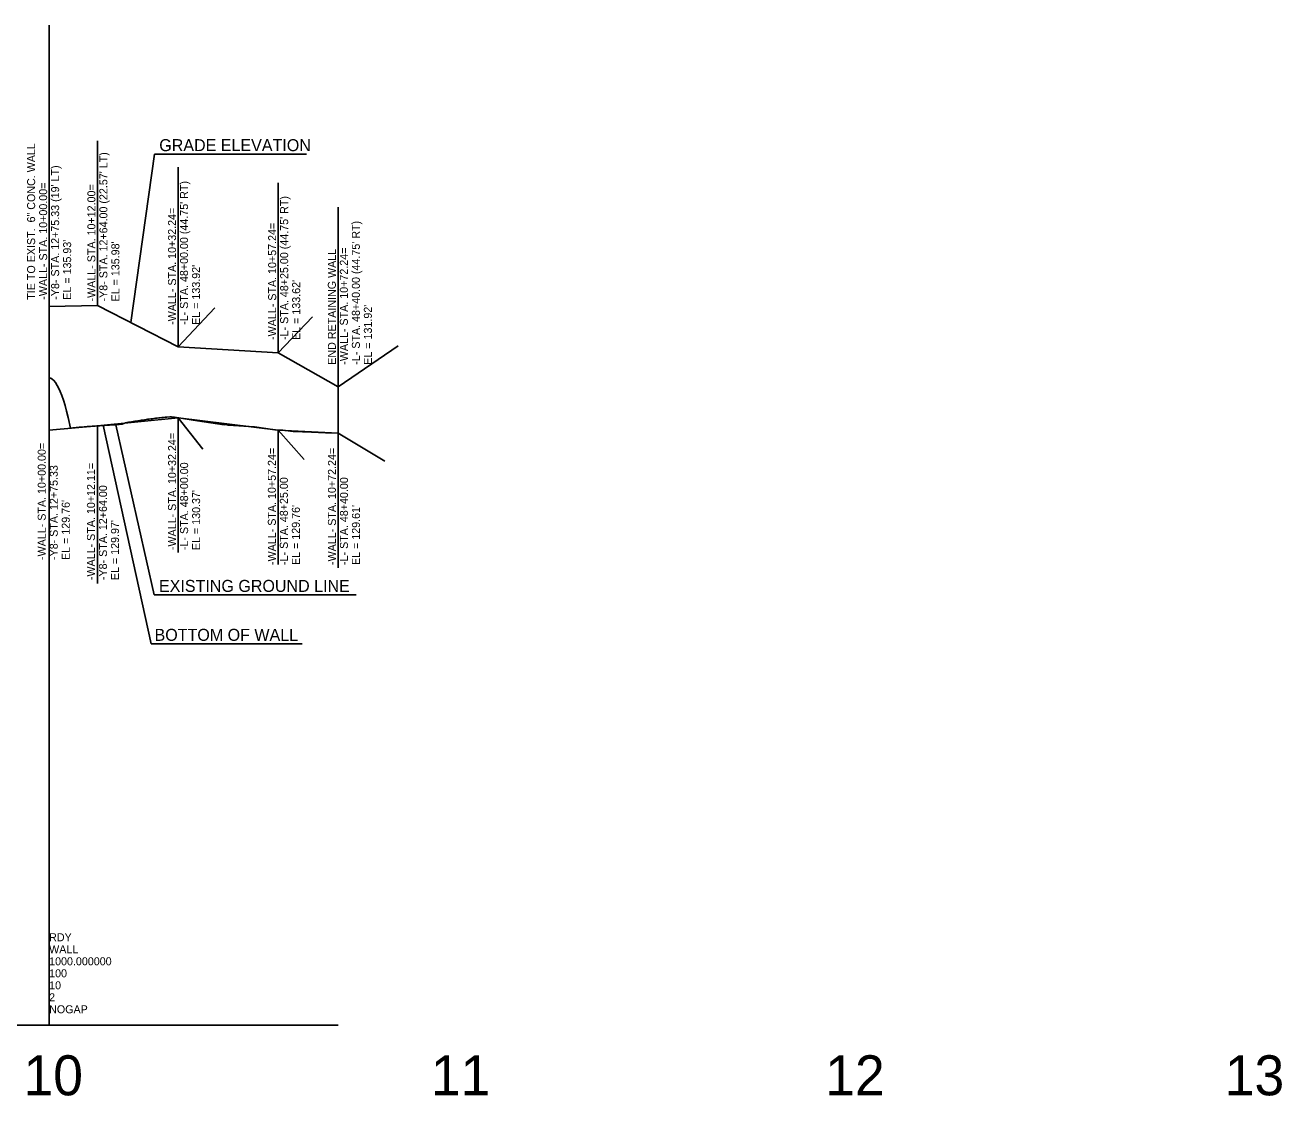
# Model space of a CAD drawing. Extents: x 1778432 to 1784301, y 601022 to 621789.
# Drawn here: x 1780137 to 1780451.1, y 601021.5 to 601289.2 of the extents above; entities that cross this region are included whole.
import ezdxf

# ---------------------------------------------------------------- set-up
doc = ezdxf.new("R2010")
doc.units = 0
for name, color, linetype in [('Exist Profile Cell', 7, 'Continuous'), ('Exist Vertical Profile Ground Line', 7, 'Continuous'), ('Exist Vertical Profile Horizontal Axis Label Major', 7, 'Continuous'), ('Old_Level_10', 7, 'Continuous'), ('Prop PFL Text', 7, 'Continuous'), ('Prop XS Finish Grade', 7, 'Continuous'), ('Prop XS Retaining Wall', 7, 'Continuous'), ('Scratch_Level_1', 7, 'Continuous')]:
    doc.layers.add(name, color=color, linetype=linetype)

msp = doc.modelspace()

# ---------------------------------------------------------------- linework, layer by layer
at = {"layer": 'Exist Profile Cell'}
for q in [(1780142.96, 601289.19), (1780215.2, 601039.19), (1780142.96, 601039.19)]:
    msp.add_line((1780142.96, 601039.19), q, dxfattribs=at)
at = {"layer": 'Exist Vertical Profile Ground Line'}
msp.add_lwpolyline([(1780142.96, 601200.93), (1780143.36, 601200.91), (1780143.75, 601200.72), (1780144.15, 601200.39), (1780144.55, 601199.9), (1780145, 601199.14), (1780145.34, 601198.51), (1780145.74, 601197.64), (1780146.14, 601196.62), (1780146.53, 601195.45), (1780146.93, 601194.14), (1780147.33, 601192.69), (1780147.72, 601191.09), (1780148.3, 601188.47), (1780148.91, 601188.52), (1780149.31, 601188.56), (1780149.71, 601188.59), (1780150.11, 601188.63), (1780150.5, 601188.66), (1780150.9, 601188.69), (1780151.3, 601188.73), (1780151.69, 601188.76), (1780152.09, 601188.79), (1780152.49, 601188.83), (1780152.88, 601188.86), (1780153.28, 601188.89), (1780153.68, 601188.92), (1780154.08, 601188.95), (1780154.47, 601188.98), (1780154.87, 601189.01), (1780155.27, 601189.04), (1780155.66, 601189.07), (1780156.06, 601189.1), (1780156.46, 601189.13), (1780156.85, 601189.15), (1780157.25, 601189.18), (1780157.65, 601189.2), (1780158.05, 601189.23), (1780158.44, 601189.25), (1780158.84, 601189.27), (1780159.24, 601189.29), (1780159.63, 601189.31), (1780160.03, 601189.34), (1780160.43, 601189.35), (1780161.22, 601189.44), (1780161.62, 601189.6), (1780162.03, 601189.77), (1780162.41, 601189.84), (1780162.81, 601189.91), (1780163.21, 601189.98), (1780163.6, 601190.05), (1780164, 601190.11), (1780164.4, 601190.18), (1780164.79, 601190.24), (1780165.19, 601190.31), (1780165.59, 601190.37), (1780165.98, 601190.43), (1780166.38, 601190.49), (1780166.78, 601190.55), (1780167.18, 601190.6), (1780167.57, 601190.66), (1780167.97, 601190.71), (1780168.37, 601190.76), (1780168.76, 601190.82), (1780169.16, 601190.86), (1780169.56, 601190.91), (1780169.95, 601190.96), (1780170.35, 601191), (1780170.75, 601191.05), (1780171.15, 601191.09), (1780171.54, 601191.13), (1780171.94, 601191.17), (1780172.34, 601191.2), (1780173.13, 601191.25), (1780173.53, 601191.25), (1780174.32, 601191.2), (1780180, 601190.32), (1780186.7, 601189.32), (1780187.13, 601189.34), (1780187.67, 601189.21), (1780194.25, 601188.81), (1780199.36, 601188.02), (1780201.38, 601187.92), (1780203.99, 601187.62), (1780208.51, 601187.44), (1780212.01, 601187.29), (1780215.2, 601187.22)], dxfattribs=at)
at = {"layer": 'Old_Level_10'}
for p, q in [((1780169.28, 601256.96), (1780163.36, 601214.84)), ((1780169.28, 601256.96), (1780207.28, 601256.96)), ((1780156.46, 601189.17), (1780168.5, 601134.56)), ((1780159.63, 601189.31), (1780169.21, 601146.8)), ((1780169.21, 601146.8), (1780219.73, 601146.8)), ((1780168.5, 601134.56), (1780206.22, 601134.56))]:
    msp.add_line(p, q, dxfattribs=at)
at = {"layer": 'Prop XS Finish Grade'}
for p, q in [((1780175.2, 601191.04), (1780200.2, 601187.99)), ((1780200.2, 601187.99), (1780215.2, 601187.24))]:
    msp.add_line(p, q, dxfattribs=at)
msp.add_lwpolyline([(1780142.96, 601187.98), (1780155.07, 601189.03), (1780175.2, 601191.04)], dxfattribs=at)
at = {"layer": 'Prop XS Retaining Wall'}
for p, q in [((1780142.96, 601218.82), (1780142.96, 601261.27)), ((1780155.07, 601219.08), (1780155.07, 601260.25)), ((1780175.2, 601208.79), (1780175.2, 601253.66)), ((1780200.2, 601207.29), (1780200.2, 601249.79)), ((1780215.2, 601198.79), (1780215.2, 601243.66)), ((1780142.96, 601218.82), (1780142.96, 601187.98)), ((1780175.2, 601208.79), (1780200.2, 601207.29)), ((1780200.2, 601207.29), (1780215.2, 601198.79)), ((1780215.2, 601198.79), (1780215.2, 601187.24)), ((1780175.2, 601157.38), (1780175.2, 601191.06)), ((1780142.96, 601154.58), (1780142.96, 601187.98)), ((1780155.07, 601149.66), (1780155.07, 601189.03)), ((1780200.2, 601154.33), (1780200.2, 601188.01)), ((1780215.2, 601153.56), (1780215.2, 601187.24))]:
    msp.add_line(p, q, dxfattribs=at)
msp.add_lwpolyline([(1780142.96, 601218.82), (1780155.07, 601219.08), (1780175.2, 601208.79)], dxfattribs=at)
at = {"layer": 'Scratch_Level_1'}
for p, q in [((1780175.2, 601208.79), (1780184.38, 601218.53)), ((1780200.2, 601207.29), (1780208.77, 601216.26)), ((1780215.2, 601198.79), (1780230.16, 601209.02)), ((1780175.2, 601191.04), (1780181.38, 601183.16)), ((1780200.2, 601187.99), (1780206.7, 601180.58)), ((1780215.2, 601187.24), (1780226.86, 601180.16)), ((1780142.96, 601039.19), (1778431.51, 601039.19))]:
    msp.add_line(p, q, dxfattribs=at)

# ---------------------------------------------------------------- texts
at = {"layer": 'Exist Profile Cell'}
for s, p in [('RDY', (1780142.96, 601060.19)), ('WALL', (1780142.96, 601057.19)), ('1000.000000', (1780142.96, 601054.19)), ('100', (1780142.96, 601051.19)), ('10', (1780142.96, 601048.19)), ('2', (1780142.96, 601045.19)), ('NOGAP', (1780142.96, 601042.19))]:
    msp.add_text(s, height=2, dxfattribs=at).set_placement(p)
at = {"layer": 'Exist Vertical Profile Horizontal Axis Label Major'}
for s, p in [('10', (1780136.54, 601021.69)), ('11', (1780238.38, 601021.69)), ('12', (1780336.93, 601021.69)), ('13', (1780436.77, 601021.69))]:
    msp.add_text(s, height=10, dxfattribs=at).set_placement(p)
at = {"layer": 'Old_Level_10'}
for s, p in [('GRADE ELEVATION', (1780170.48, 601257.69)), ('EXISTING GROUND LINE', (1780170.41, 601147.52)), ('BOTTOM OF WALL', (1780169.3, 601135.29))]:
    msp.add_text(s, height=3, dxfattribs=at).set_placement(p)
at = {"layer": 'Prop PFL Text'}
for s, p in [('TIE TO EXIST.  6" CONC. WALL', (1780139.46, 601220.55)), ("-Y8- STA. 12+64.00 (22.57' LT)", (1780157.52, 601220.12)), ("-Y8- STA. 12+75.33 (19' LT)", (1780145.46, 601220.55)), ('-WALL- STA. 10+00.00=', (1780142.46, 601220.55)), ('-WALL- STA. 10+12.00=', (1780154.52, 601220.12)), ("-L- STA. 48+00.00 (44.75' RT)", (1780177.67, 601214.27)), ("-L- STA. 48+25.00 (44.75' RT)", (1780202.7, 601210.5)), ('-WALL- STA. 10+32.24=', (1780174.67, 601214.27)), ('-WALL- STA. 10+57.24=', (1780199.7, 601210.5)), ("-L- STA. 48+40.00 (44.75' RT)", (1780220.62, 601204.3)), ("EL = 135.93'", (1780148.46, 601220.55)), ("EL = 135.98'", (1780160.52, 601220.12)), ('END RETAINING WALL', (1780214.62, 601204.3)), ('-WALL- STA. 10+72.24=', (1780217.62, 601204.3)), ("EL = 133.92'", (1780180.67, 601214.27)), ("EL = 133.62'", (1780205.7, 601210.5)), ("EL = 131.92'", (1780223.62, 601204.3)), ('-WALL- STA. 10+00.00=', (1780142.11, 601155.5)), ('-WALL- STA. 10+32.24=', (1780174.69, 601157.97)), ('-WALL- STA. 10+57.24=', (1780199.62, 601154.25)), ('-WALL- STA. 10+72.24=', (1780214.64, 601154.25)), ('-Y8- STA. 12+75.33', (1780145.11, 601155.5)), ('-WALL- STA. 10+12.11=', (1780154.41, 601150.47)), ('-L- STA. 48+00.00', (1780177.69, 601157.97)), ('-L- STA. 48+25.00', (1780202.62, 601154.25)), ('-L- STA. 48+40.00', (1780217.64, 601154.25)), ('-Y8- STA. 12+64.00', (1780157.41, 601150.47)), ("EL = 130.37'", (1780180.69, 601157.97)), ("EL = 129.76'", (1780148.11, 601155.5)), ("EL = 129.76'", (1780205.62, 601154.25)), ("EL = 129.61'", (1780220.64, 601154.25)), ("EL = 129.97'", (1780160.41, 601150.47))]:
    msp.add_text(s, height=2, rotation=90, dxfattribs=at).set_placement(p)

doc.saveas('drawing.dxf')
